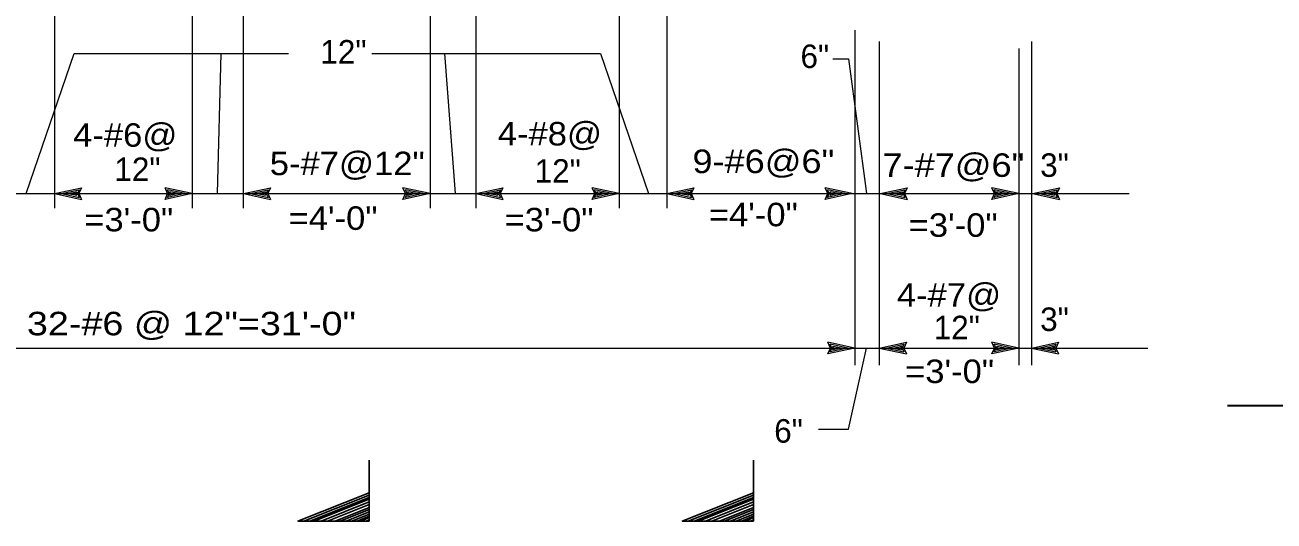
# Model space of a CAD drawing. Extents: x -22.3 to 19.7, y -11.8 to 18.2.
# Drawn here: x -13.77 to -7.13, y -1.04 to 1.6 of the extents above; entities that cross this region are included whole.
import ezdxf
from ezdxf.enums import TextEntityAlignment as Align

# ---------------------------------------------------------------- set-up
doc = ezdxf.new("R2010")
doc.units = 0
doc.header["$LTSCALE"] = 0.05
doc.layers.add('1', color=7, linetype='Continuous', lineweight=13)
doc.layers.add('2', color=7, linetype='Continuous', lineweight=13)

msp = doc.modelspace()

# ---------------------------------------------------------------- linework, layer by layer
at = {"layer": '1'}
for p, q in [((-13.61742, 1.89131), (-13.61742, 0.62531)), ((-12.88542, 1.89131), (-12.88542, 0.62531)), ((-12.61342, 1.89131), (-12.61342, 0.62531)), ((-11.61942, 1.89131), (-11.61942, 0.62531)), ((-11.37642, 1.89131), (-11.37642, 0.62531)), ((-10.61342, 1.89131), (-10.61342, 0.62531)), ((-10.36042, 1.89131), (-10.36042, 0.62531)), ((-9.35942, 1.57131), (-9.35942, -0.20969)), ((-9.22942, 1.51231), (-9.22942, -0.20969)), ((-8.48642, 1.47331), (-8.48642, -0.20969)), ((-8.42042, 1.51231), (-8.42042, -0.20969)), ((-13.76842, 0.70231), (-13.51342, 1.44731)), ((-13.51342, 1.44731), (-12.37242, 1.44731)), ((-12.74942, 0.70231), (-12.73042, 1.44731)), ((-11.92842, 1.44731), (-10.71242, 1.44731)), ((-11.54242, 1.44731), (-11.48542, 0.70231)), ((-10.71242, 1.44731), (-10.45742, 0.70231)), ((-13.61742, 0.70231), (-13.47342, 0.73331)), ((-12.88542, 0.70231), (-13.02942, 0.73331)), ((-12.61242, 0.70231), (-12.46842, 0.73331)), ((-11.61942, 0.70231), (-11.76342, 0.73331)), ((-11.37642, 0.70231), (-11.23242, 0.73331)), ((-10.61342, 0.70231), (-10.75742, 0.73331)), ((-10.35942, 0.70231), (-10.21542, 0.73331)), ((-9.37342, 0.70231), (-9.51742, 0.73331)), ((-9.22442, 0.70231), (-9.08042, 0.73331)), ((-8.48642, 0.70231), (-8.63042, 0.73331)), ((-8.41442, 0.70231), (-8.27042, 0.73331)), ((-13.61742, 0.70231), (-13.47342, 0.67131)), ((-13.58042, 0.70231), (-13.48642, 0.72231)), ((-13.58042, 0.70231), (-13.48642, 0.68231)), ((-13.54442, 0.70231), (-13.49942, 0.71231)), ((-13.54442, 0.70231), (-13.49942, 0.69331)), ((-13.49942, 0.71231), (-13.50342, 0.70231)), ((-13.50342, 0.70231), (-13.49942, 0.69331)), ((-13.48642, 0.72231), (-13.49542, 0.70231)), ((-13.49542, 0.70231), (-13.48642, 0.68231)), ((-12.88542, 0.70231), (-13.02942, 0.67131)), ((-12.92242, 0.70231), (-13.01642, 0.72231)), ((-13.00742, 0.70231), (-13.01642, 0.72231)), ((-12.92242, 0.70231), (-13.01642, 0.68231)), ((-13.01642, 0.68231), (-13.00742, 0.70231)), ((-12.95842, 0.70231), (-13.00342, 0.71131)), ((-12.99942, 0.70231), (-13.00342, 0.71131)), ((-12.95842, 0.70231), (-13.00342, 0.69231)), ((-13.00342, 0.69231), (-12.99942, 0.70231)), ((-12.61242, 0.70231), (-12.46842, 0.67131)), ((-12.57542, 0.70231), (-12.48142, 0.72231)), ((-12.57542, 0.70231), (-12.48142, 0.68231)), ((-12.53942, 0.70231), (-12.49442, 0.71231)), ((-12.53942, 0.70231), (-12.49442, 0.69331)), ((-12.49442, 0.71231), (-12.49842, 0.70231)), ((-12.49842, 0.70231), (-12.49442, 0.69331)), ((-12.48142, 0.72231), (-12.49042, 0.70231)), ((-12.49042, 0.70231), (-12.48142, 0.68231)), ((-11.61942, 0.70231), (-11.76342, 0.67131)), ((-11.65642, 0.70231), (-11.75042, 0.72231)), ((-11.74142, 0.70231), (-11.75042, 0.72231)), ((-11.65642, 0.70231), (-11.75042, 0.68231)), ((-11.75042, 0.68231), (-11.74142, 0.70231)), ((-11.69242, 0.70231), (-11.73742, 0.71131)), ((-11.73342, 0.70231), (-11.73742, 0.71131)), ((-11.69242, 0.70231), (-11.73742, 0.69231)), ((-11.73742, 0.69231), (-11.73342, 0.70231)), ((-11.37642, 0.70231), (-11.23242, 0.67131)), ((-11.33942, 0.70231), (-11.24542, 0.72231)), ((-11.33942, 0.70231), (-11.24542, 0.68231)), ((-11.30342, 0.70231), (-11.25842, 0.71231)), ((-11.30342, 0.70231), (-11.25842, 0.69331)), ((-11.25842, 0.71231), (-11.26242, 0.70231)), ((-11.26242, 0.70231), (-11.25842, 0.69331)), ((-11.24542, 0.72231), (-11.25442, 0.70231)), ((-11.25442, 0.70231), (-11.24542, 0.68231)), ((-10.61342, 0.70231), (-10.75742, 0.67131)), ((-10.65042, 0.70231), (-10.74442, 0.72231)), ((-10.73542, 0.70231), (-10.74442, 0.72231)), ((-10.65042, 0.70231), (-10.74442, 0.68231)), ((-10.74442, 0.68231), (-10.73542, 0.70231)), ((-10.68642, 0.70231), (-10.73142, 0.71131)), ((-10.72742, 0.70231), (-10.73142, 0.71131)), ((-10.68642, 0.70231), (-10.73142, 0.69231)), ((-10.73142, 0.69231), (-10.72742, 0.70231)), ((-10.35942, 0.70231), (-10.21542, 0.67131)), ((-10.32242, 0.70231), (-10.22842, 0.72231)), ((-10.32242, 0.70231), (-10.22842, 0.68231)), ((-10.28642, 0.70231), (-10.24142, 0.71231)), ((-10.28642, 0.70231), (-10.24142, 0.69331)), ((-10.24142, 0.71231), (-10.24542, 0.70231)), ((-10.24542, 0.70231), (-10.24142, 0.69331)), ((-10.22842, 0.72231), (-10.23742, 0.70231)), ((-10.23742, 0.70231), (-10.22842, 0.68231)), ((-9.37342, 0.70231), (-9.51742, 0.67131)), ((-9.41042, 0.70231), (-9.50442, 0.72231)), ((-9.49542, 0.70231), (-9.50442, 0.72231)), ((-9.41042, 0.70231), (-9.50442, 0.68231)), ((-9.50442, 0.68231), (-9.49542, 0.70231)), ((-9.44642, 0.70231), (-9.49142, 0.71131)), ((-9.48742, 0.70231), (-9.49142, 0.71131)), ((-9.44642, 0.70231), (-9.49142, 0.69231)), ((-9.49142, 0.69231), (-9.48742, 0.70231)), ((-9.22442, 0.70231), (-9.08042, 0.67131)), ((-9.18742, 0.70231), (-9.09342, 0.72231)), ((-9.18742, 0.70231), (-9.09342, 0.68231)), ((-9.15142, 0.70231), (-9.10642, 0.71231)), ((-9.15142, 0.70231), (-9.10642, 0.69331)), ((-9.10642, 0.71231), (-9.11042, 0.70231)), ((-9.11042, 0.70231), (-9.10642, 0.69331)), ((-9.09342, 0.72231), (-9.10242, 0.70231)), ((-9.10242, 0.70231), (-9.09342, 0.68231)), ((-8.48642, 0.70231), (-8.63042, 0.67131)), ((-8.52342, 0.70231), (-8.61742, 0.72231)), ((-8.60842, 0.70231), (-8.61742, 0.72231)), ((-8.52342, 0.70231), (-8.61742, 0.68231)), ((-8.61742, 0.68231), (-8.60842, 0.70231)), ((-8.55942, 0.70231), (-8.60442, 0.71131)), ((-8.60042, 0.70231), (-8.60442, 0.71131)), ((-8.55942, 0.70231), (-8.60442, 0.69231)), ((-8.60442, 0.69231), (-8.60042, 0.70231)), ((-8.41442, 0.70231), (-8.27042, 0.67131)), ((-8.37742, 0.70231), (-8.28342, 0.72231)), ((-8.37742, 0.70231), (-8.28342, 0.68231)), ((-8.34142, 0.70231), (-8.29642, 0.71231)), ((-8.34142, 0.70231), (-8.29642, 0.69331)), ((-8.29642, 0.71231), (-8.30042, 0.70231)), ((-8.30042, 0.70231), (-8.29642, 0.69331)), ((-8.28342, 0.72231), (-8.29242, 0.70231)), ((-8.29242, 0.70231), (-8.28342, 0.68231)), ((-9.35942, -0.11969), (-9.50342, -0.08869)), ((-9.35942, -0.11969), (-9.50342, -0.15069)), ((-9.39642, -0.11969), (-9.49042, -0.09969)), ((-9.48142, -0.11969), (-9.49042, -0.09969)), ((-9.39642, -0.11969), (-9.49042, -0.13969)), ((-9.49042, -0.13969), (-9.48142, -0.11969)), ((-9.43242, -0.11969), (-9.47742, -0.11069)), ((-9.47342, -0.11969), (-9.47742, -0.11069)), ((-9.43242, -0.11969), (-9.47742, -0.12969)), ((-9.47742, -0.12969), (-9.47342, -0.11969)), ((-9.22942, -0.11969), (-9.08542, -0.08869)), ((-9.22942, -0.11969), (-9.08542, -0.15069)), ((-9.19242, -0.11969), (-9.09842, -0.09969)), ((-9.19242, -0.11969), (-9.09842, -0.13969)), ((-9.15642, -0.11969), (-9.11142, -0.10969)), ((-9.15642, -0.11969), (-9.11142, -0.12869)), ((-9.11142, -0.10969), (-9.11542, -0.11969)), ((-9.11542, -0.11969), (-9.11142, -0.12869)), ((-9.09842, -0.09969), (-9.10742, -0.11969)), ((-9.10742, -0.11969), (-9.09842, -0.13969)), ((-8.48642, -0.11969), (-8.63042, -0.08869)), ((-8.48642, -0.11969), (-8.63042, -0.15069)), ((-8.52342, -0.11969), (-8.61742, -0.09969)), ((-8.60842, -0.11969), (-8.61742, -0.09969)), ((-8.52342, -0.11969), (-8.61742, -0.13969)), ((-8.61742, -0.13969), (-8.60842, -0.11969)), ((-8.55942, -0.11969), (-8.60442, -0.11069)), ((-8.60042, -0.11969), (-8.60442, -0.11069)), ((-8.55942, -0.11969), (-8.60442, -0.12969)), ((-8.60442, -0.12969), (-8.60042, -0.11969)), ((-8.42042, -0.11969), (-8.27642, -0.08869)), ((-8.42042, -0.11969), (-8.27642, -0.15069)), ((-8.38342, -0.11969), (-8.28942, -0.09969)), ((-8.38342, -0.11969), (-8.28942, -0.13969)), ((-8.34742, -0.11969), (-8.30242, -0.10969)), ((-8.34742, -0.11969), (-8.30242, -0.12869)), ((-8.30242, -0.10969), (-8.30642, -0.11969)), ((-8.30642, -0.11969), (-8.30242, -0.12869)), ((-8.28942, -0.09969), (-8.29842, -0.11969)), ((-8.29842, -0.11969), (-8.28942, -0.13969))]:
    msp.add_line(p, q, dxfattribs=at)
at = {"layer": '1', "lineweight": 35}
msp.add_line((-7.37642, -0.42569), (-2.28642, -0.42569), dxfattribs=at)
at = {"layer": '1'}
for points in [[(-9.47742, 1.41931), (-9.39242, 1.41931), (-9.29742, 0.70231)], [(-13.47342, 0.73331), (-13.48742, 0.70231), (-13.47342, 0.67131)], [(-13.02942, 0.67131), (-13.01542, 0.70231), (-13.02942, 0.73331)], [(-12.46842, 0.73331), (-12.48242, 0.70231), (-12.46842, 0.67131)], [(-11.76342, 0.67131), (-11.74942, 0.70231), (-11.76342, 0.73331)], [(-11.23242, 0.73331), (-11.24642, 0.70231), (-11.23242, 0.67131)], [(-10.75742, 0.67131), (-10.74342, 0.70231), (-10.75742, 0.73331)], [(-10.21542, 0.73331), (-10.22942, 0.70231), (-10.21542, 0.67131)], [(-9.51742, 0.67131), (-9.50342, 0.70231), (-9.51742, 0.73331)], [(-9.08042, 0.73331), (-9.09442, 0.70231), (-9.08042, 0.67131)], [(-8.63042, 0.67131), (-8.61642, 0.70231), (-8.63042, 0.73331)], [(-8.27042, 0.73331), (-8.28442, 0.70231), (-8.27042, 0.67131)], [(-18.23142, 0.70231), (-17.08742, 0.70231), (-16.99942, 0.70231), (-13.87442, 0.70231), (-13.61742, 0.70231), (-12.88542, 0.70231), (-12.61242, 0.70231), (-11.61942, 0.70231), (-11.37642, 0.70231), (-10.61342, 0.70231), (-10.35942, 0.70231), (-9.37342, 0.70231), (-9.22442, 0.70231), (-8.48642, 0.70231), (-8.41442, 0.70231), (-7.89942, 0.70231)], [(-18.20842, -0.11969), (-17.08742, -0.11969), (-16.99942, -0.11969), (-9.35942, -0.11969), (-9.22942, -0.11969), (-8.48642, -0.11969), (-8.42042, -0.11969), (-7.80142, -0.11969)], [(-9.55242, -0.55169), (-9.39242, -0.55169), (-9.29742, -0.11969)], [(-9.50342, -0.15069), (-9.48942, -0.11969), (-9.50342, -0.08869)], [(-9.08542, -0.08869), (-9.09942, -0.11969), (-9.08542, -0.15069)], [(-8.63042, -0.15069), (-8.61642, -0.11969), (-8.63042, -0.08869)], [(-8.27642, -0.08869), (-8.29042, -0.11969), (-8.27642, -0.15069)]]:
    msp.add_lwpolyline(points, dxfattribs=at)
at = {"layer": '2', "lineweight": 25}
for p, q in [((-11.94342, -1.03969), (-11.94342, -0.71569)), ((-9.89842, -1.03969), (-9.89842, -0.71569)), ((-12.29142, -1.03969), (-11.94342, -0.90169)), ((-12.25842, -1.03969), (-11.94342, -0.91469)), ((-12.23542, -1.03969), (-11.94342, -0.92369)), ((-10.24642, -1.03969), (-9.89842, -0.90169)), ((-10.21342, -1.03969), (-9.89842, -0.91469)), ((-10.19042, -1.03969), (-9.89842, -0.92369)), ((-12.19942, -1.03969), (-11.94342, -0.93769)), ((-12.16542, -1.03969), (-11.94342, -0.95169)), ((-12.12442, -1.03969), (-11.94342, -0.96769)), ((-12.09742, -1.03969), (-11.94342, -0.97869)), ((-12.06542, -1.03969), (-11.94342, -0.99069)), ((-10.15442, -1.03969), (-9.89842, -0.93769)), ((-10.12042, -1.03969), (-9.89842, -0.95169)), ((-10.07942, -1.03969), (-9.89842, -0.96769)), ((-10.05242, -1.03969), (-9.89842, -0.97869)), ((-10.02042, -1.03969), (-9.89842, -0.99069)), ((-12.03642, -1.03969), (-11.94342, -1.00269)), ((-12.00742, -1.03969), (-11.94342, -1.01369)), ((-11.98742, -1.03969), (-11.94342, -1.02169)), ((-11.96042, -1.03969), (-11.94342, -1.03269)), ((-9.99142, -1.03969), (-9.89842, -1.00269)), ((-9.96242, -1.03969), (-9.89842, -1.01369)), ((-9.94242, -1.03969), (-9.89842, -1.02169)), ((-9.91542, -1.03969), (-9.89842, -1.03269))]:
    msp.add_line(p, q, dxfattribs=at)
for points in [[(-11.94342, -1.03969), (-12.32242, -1.03969), (-11.94342, -0.88969)], [(-9.89842, -1.03969), (-10.27742, -1.03969), (-9.89842, -0.88969)]]:
    msp.add_lwpolyline(points, dxfattribs=at)

# ---------------------------------------------------------------- texts
at = {"layer": '1'}
for s, p in [('12"', (-12.07992, 1.39431)), ('6"', (-9.57242, 1.37031)), ('12"', (-13.17592, 0.76931)), ('12"', (-10.93992, 0.76031)), ('12"', (-8.81692, -0.07269))]:
    msp.add_text(s, height=0.125, dxfattribs=at).set_placement(p, align=Align.CENTER)
for s, width, p in [('4-#6@', 1.1, (-13.24092, 0.95131)), ('4-#8@', 1.1, (-10.98192, 0.95831)), ('5-#7@12"', 1.1, (-12.05992, 0.80031)), ('9-#6@6"', 1.15, (-9.84592, 0.81131)), ('7-#7@6"', 1.15, (-8.83492, 0.79131)), ('=3\'-0"', 1.1, (-13.22242, 0.50131)), ('=4\'-0"', 1.1, (-12.13542, 0.50931)), ('=3\'-0"', 1.1, (-10.98642, 0.50131)), ('=4\'-0"', 1.1, (-9.89942, 0.52831)), ('=3\'-0"', 1.1, (-8.83642, 0.47231)), ('4-#7@', 1.1, (-8.85842, 0.10031)), ('32-#6 @ 12"=31\'-0"', 1.2, (-12.88892, -0.05169)), ('=3\'-0"', 1.1, (-8.85542, -0.30569))]:
    msp.add_text(s, height=0.125, dxfattribs=dict(at, width=width)).set_placement(p, align=Align.CENTER)
for s, p in [('3"', (-8.37342, 0.79131)), ('3"', (-8.37342, -0.02869)), ('6"', (-9.78842, -0.62269))]:
    msp.add_text(s, height=0.125, dxfattribs=at).set_placement(p)

doc.saveas('drawing.dxf')
